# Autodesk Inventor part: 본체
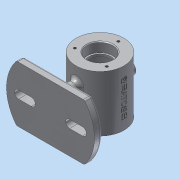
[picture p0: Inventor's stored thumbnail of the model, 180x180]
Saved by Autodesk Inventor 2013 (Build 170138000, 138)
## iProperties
Created: 2017-12
Part Number: 본체
Material: 알루미늄 6061
Document SubType Name: Modeling
Designer: Administrator
Density: 2.71 g/cm^3
Mass: 467.694 g
Surface Area: 486.438 cm^2
Volume: 172.581 cm^3
Author: Administrator
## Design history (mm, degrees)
sketch "스케치1"
  geometry: C1 r 30 at (0, 0); 1 further point
  constraints: 1 centre point, 1 coincident
  dimensions: "d2" = 30 radius of C1
extrude "돌출1" new body sketch "스케치1" stored distance "d3" = 70; taper "d4" = 0 deg
sketch "스케치2"
  geometry: C1 r 30 at (0, 0) reference; 1 further point
  constraints: 1 vertical alignment
  dimensions: "d5" = 23 distance of C1.centre point (0, 23)
hole "구멍1" sketch "스케치2" at (0, 23) diameter "d6" = 3.242; stored, may be unused: countersink angle "d10" = 90 deg, drill point angle "d12" = 118 deg; dims "d7" = 8, "d8" = 4, "d9" = 2, "d11" = 10
node "작업 평면1"
sketch "스케치3"
  geometry: C1 r 8 at (0, 0); 1 further point
  constraints: 1 centre point, 1 coincident
  dimensions: "d17" = 8 radius of C1
extrude "돌출2" join sketch "스케치3" stored distance "d18" = 70; taper "d19" = 0 deg
hole "구멍2" diameter "d22" = 28; stored, may be unused: countersink angle "d26" = 90 deg, drill point angle "d28" = 0 deg; dims "d23" = 28, "d24" = 32, "d25" = 12, "d27" = 15, "d29" = 10, "d30" = 10
hole "구멍3" diameter "d33" = 50; stored, may be unused: countersink angle "d37" = 90 deg, drill point angle "d39" = 0 deg; dims "d31" = 10, "d32" = 10, "d34" = 28, "d35" = 32, "d36" = 12, "d38" = 40
hole "구멍4" diameter "d42" = 8; stored, may be unused: countersink angle "d46" = 90 deg, drill point angle "d48" = 0 deg; dims "d40" = 10, "d41" = 10, "d43" = 28, "d44" = 32, "d45" = 12, "d47" = 40
node "작업 평면2"
sketch "스케치4"
  geometry: L1 (42.426, 35)-(-42.426, 35); L2 (42.426, -35)-(-42.426, -35); L3 (0, 35)-(0, -35); L4 (40, 5)-(24, 5); L5 (24, 5)-(32, 5); L6 (24, -5)-(40, -5); A1 r 55 centre (0, 0) between (42.426, -35) and (42.426, 35); A2 r 55 centre (0, 0) between (-42.426, 35) and (-42.426, -35); A3 r 5 centre (24, 0) between (24, 5) and (24, -5); A4 r 5 centre (40, 0) between (40, -5) and (40, 5); 2 further points
  constraints: 12 end point, 8 point on circle, 4 centre point, 4 midpoint, 4 tangent, 2 parallel, 1 coincident, 1 horizontal, 1 horizontal alignment, 1 perpendicular
  dimensions: "d51" = 70 distance between parallel lines of L2 L1; "d52" = 35 distance from line of point (0, 0) L1 (= 0.5 x d51); "d53" = 55 radius of A1; "d54" = 55 radius of A2; "d56" = 5 radius of A4; "d57" = 16 distance of A3.centre A4.centre; "d58" = 24 distance of point (0, 0) A3.centre
extrude "돌출3" join sketch "스케치4" distance "d59" = 10; taper "d60" = 0 deg
sketch "스케치5"
  geometry: L1 (42.426, 35)-(-42.426, 35) reference; L2 (-5, 15)-(-5, -15); L3 (5, -15)-(5, 15); L4 (-42.426, -35)-(42.426, -35) reference; L5 (24, 5)-(40, 5); L6 (40, -5)-(24, -5); A1 r 55 centre (0, 0) between (42.426, -35) and (42.426, 35) reference; A2 r 5 centre (0, -15) between (-5, -15) and (5, -15); A3 r 5 centre (0, 15) between (5, 15) and (-5, 15); A4 r 5 centre (40, 0) between (40, -5) and (40, 5); A5 r 5 centre (24, 0) between (24, 5) and (24, -5)
  constraints: 8 end point, 8 point on circle, 8 tangent, 4 centre point, 3 parallel, 1 horizontal alignment, 1 perpendicular, 1 vertical alignment
  dimensions: "d61" = 5 radius of A3; "d63" = 30 distance of A2.centre A3.centre; "d64" = 15 distance of A1.centre A3.centre (= 0.5 x d63); "d67" = 5 radius of A5; "d68" = 16 distance of A4.centre A5.centre; "d69" = 24 distance of A5.centre A1.centre
extrude "돌출4" join sketch "스케치5" stored distance "d65" = 10; taper "d66" = 0 deg
extrude "돌출5" cut sketch "스케치5" distance "d70" = 10; taper "d71" = 0 deg
node "작업 평면3"
sketch "스케치6"
  geometry: L1 (30, -35)-(30, 35) reference; 2 further points
  constraints: 1 coincident, 1 other
  dimensions: "d72" = 30 distance from line of point (0, 0) L1
feature "엠보싱1" sketch "스케치6" dims "d3" = 70, "d4" = 0, "d73" = 0.5, "d74" = 0
chamfer "모따기1" distance "d75" = 1; stored, may be unused: second distance "d76" = 2, angle "d77" = 45 deg
fillet "모깎기1" dims "d78" = 0.3
fillet "모깎기2" dims "d79" = 3
fillet "모깎기3" dims "d80" = 5
node "솔리드1"
pattern_circular "원형 패턴1" dims angle "d14" = 360 deg
mirror "대칭1"
mirror "대칭2"
other parameters: "d16" = 37, "d49" = -62, "d50" = 55
